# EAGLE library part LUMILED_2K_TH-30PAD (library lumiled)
Luxeon K2 LED with Thermal-Pads Place a Supply-Pin wit NET-Name 'TH' in schematic to connect all Thermal-Pads witout place the thermal gates. Place in Layout a POLYGON named 'TH' to generate a great thermal copper connected to the thermal pads. Source: 0041 Luxeon K2 on FR4 with open vias.pdf DS60.pdf
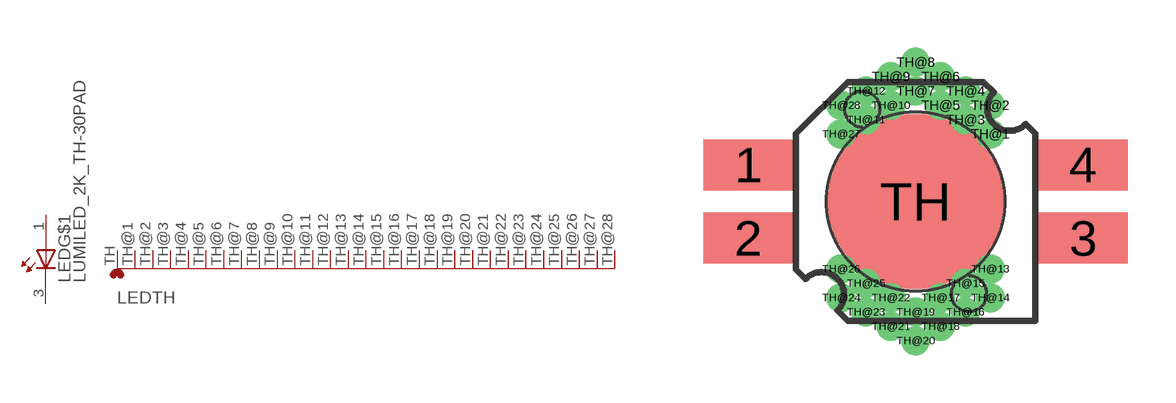
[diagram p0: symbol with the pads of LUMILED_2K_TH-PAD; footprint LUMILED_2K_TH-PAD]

Designator prefix LED; gates G$1=LED-PAD-2 TH=TH-30

## LUMILED_2K_TH-30PAD (MPN: LXK2-PB14-N00; OC_FARNELL: 1225059; OC_NEWARK: 05M0599)  [LUMILED_2K_TH-PAD]
1  G$1:A  pas
2  G$1:A  pas
3  G$1:C  pas
4  G$1:C  pas
TH  TH:TH  pwr
TH@1  TH:TH  pwr
TH@2  TH:TH  pwr
TH@3  TH:TH  pwr
TH@4  TH:TH  pwr
TH@5  TH:TH  pwr
TH@6  TH:TH  pwr
TH@7  TH:TH  pwr
TH@8  TH:TH  pwr
TH@9  TH:TH  pwr
TH@10  TH:TH  pwr
TH@11  TH:TH  pwr
TH@12  TH:TH  pwr
TH@13  TH:TH  pwr
TH@14  TH:TH  pwr
TH@15  TH:TH  pwr
TH@16  TH:TH  pwr
TH@17  TH:TH  pwr
TH@18  TH:TH  pwr
TH@19  TH:TH  pwr
TH@20  TH:TH  pwr
TH@21  TH:TH  pwr
TH@22  TH:TH  pwr
TH@23  TH:TH  pwr
TH@24  TH:TH  pwr
TH@25  TH:TH  pwr
TH@26  TH:TH  pwr
TH@27  TH:TH  pwr
TH@28  TH:TH  pwr

## Footprint LUMILED_2K_TH-PAD (pad centres in mm)
Luxeon K2 LED with Thermal-Pads Place a Supply-Pin wit NET-Name 'TH' in schematic to connect all Thermal-Pads witout place the thermal gates. Place in Layout a POLYGON named 'TH' to generate a great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
smd 2.8 x 1.6: 1 -5.25,1.15; 2 -5.25,-1.15; 3 5.25,-1.15; 4 5.25,1.15
smd 5.5 x 5.5: TH 0,0
drill 0.4 pad 0.6 round: TH@1 2.338,2.119; TH@2 2.338,3.019; TH@3 1.559,2.569; TH@4 1.559,3.469; TH@5 0.779,3.019; TH@6 0.779,3.919; TH@7 0,3.469; TH@8 0,4.369; TH@9 -0.779,3.919; TH@10 -0.779,3.019; TH@11 -1.559,2.569; TH@12 -1.559,3.469; TH@13 2.338,-2.119; TH@14 2.338,-3.019; TH@15 1.559,-2.569; TH@16 1.559,-3.469; TH@17 0.779,-3.019; TH@18 0.779,-3.919; TH@19 0,-3.469; TH@20 0,-4.369; TH@21 -0.779,-3.919; TH@22 -0.779,-3.019; TH@23 -1.559,-3.469; TH@24 -2.338,-3.019; TH@25 -1.559,-2.569; TH@26 -2.338,-2.119; TH@27 -2.338,2.119; TH@28 -2.338,3.019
